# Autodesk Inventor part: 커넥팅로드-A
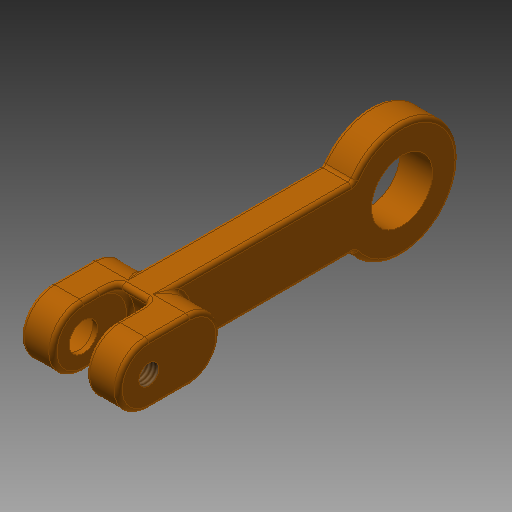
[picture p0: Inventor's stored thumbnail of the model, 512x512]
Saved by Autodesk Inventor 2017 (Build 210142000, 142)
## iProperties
Created: 2018-01
Part Number: 커넥팅로드-A
Material: 알루미늄 6061
Document SubType Name: Modeling
Designer: mduedu
Density: 2.71 g/cm^3
Mass: 4.48976 g
Surface Area: 15.547 cm^2
Volume: 1.65674 cm^3
Appearance: 주황색
Author: mduedu
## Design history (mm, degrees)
sketch "스케치1"
  geometry: L1 (0, 0)-(0, 35); L2 (3.75, 35)-(3.75, 5.911); L3 (-3.75, 35)-(-3.75, 5.911); A1 r 7 centre (0, 0) between (3.75, 5.911) and (-3.75, 5.911); A2 r 3.75 centre (0, 35) between (3.75, 35) and (-3.75, 35); 1 further point
  constraints: 6 end point, 4 point on circle, 2 centre point, 2 coincident, 2 parallel, 2 tangent, 1 vertical
  dimensions: "d1" = 35 distance of L1.start L1.end; "d2" = 7.5 diameter of A2; "d3" = 14 diameter of A1
extrude "돌출1" new body sketch "스케치1" stored distance "d4" = 4; taper "d5" = 0 deg
sketch "스케치2"
  geometry: L1 (-3.75, 35)-(-3.75, 30); L2 (3.75, 35)-(3.75, 30); A1 r 3.75 centre (0, 35) between (3.75, 35) and (-3.75, 35) reference; A2 r 3.75 centre (0, 35) between (3.75, 35) and (-3.75, 35); A3 r 3.75 centre (0, 30) between (-3.75, 30) and (3.75, 30); 1 further point
  constraints: 4 end point, 4 point on circle, 2 centre point, 2 tangent, 1 coincident, 1 equal radius, 1 point on line, 1 vertical alignment
  dimensions: "d6" = 5 distance of A3.centre A1.centre
extrude "돌출2" join sketch "스케치2" stored distance "d7" = 12; taper "d8" = 0 deg
sketch "스케치3"
  geometry: L1 (3.75, 35)-(3.75, 33); L2 (-3.75, 35)-(-3.75, 33); A1 r 3.75 centre (0, 35) between (3.75, 35) and (-3.75, 35) reference; A2 r 3.75 centre (0, 35) between (3.75, 35) and (-3.75, 35); A3 r 3.75 centre (0, 33) between (-3.75, 33) and (3.75, 33); 1 further point
  constraints: 4 end point, 4 point on circle, 3 tangent, 2 centre point, 1 coincident, 1 equal radius, 1 parallel, 1 point on line
  dimensions: "d9" = 2 distance of A3.centre A1.centre
extrude "돌출3" cut sketch "스케치3" stored distance "d10" = 4; taper "d11" = 0 deg
fillet "모깎기5" dims "d16" = 0.5
fillet "모깎기6" dims "d17" = 0.5
fillet "모깎기7" dims "d18" = 0.5
fillet "모깎기8" dims "d19" = 0.5
hole "구멍1" diameter "d22" = 7.5; stored, may be unused: countersink angle "d26" = 90 deg, drill point angle "d28" = 118 deg; dims "d20" = 10, "d21" = 10, "d23" = 6, "d24" = 4, "d25" = 2, "d27" = 8
sketch "스케치4"
  geometry: A1 r 3.75 centre (35, 0) between (35, -3.75) and (35, 3.75) reference; 2 further points
  constraints: 1 coincident
sketch "스케치5"
  geometry: A1 r 3.75 centre (35, 0) between (35, -3.75) and (35, 3.75) reference; 1 further point
  constraints: 1 coincident
hole "구멍2" sketch "스케치5" at (35, 0) diameter "d29" = 2.459; stored, may be unused: countersink angle "d33" = 90 deg, drill point angle "d35" = 0 deg; dims "d30" = 6, "d31" = 4, "d32" = 2, "d34" = 8
hole "구멍5" diameter "d45" = 3.5; stored, may be unused: countersink angle "d49" = 90 deg, drill point angle "d51" = 0 deg; dims "d46" = 6, "d47" = 6, "d48" = 3.4, "d50" = 5, "d52" = 10, "d53" = 10
node "솔리드1"
